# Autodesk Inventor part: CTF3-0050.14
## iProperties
Shininess: 64.0
Length Units: 11269
Angle Units: 11279
Time Units: 11290
Mass Units: 11283
Length Display Precision: 3
Angle Display Precision: 2
Compacted: True
Part Number: CTF3-0050.14
Document SubType Name: Modeling
Created: 2004-01
Designer: Lollo
Density: 0.0
Volumn: 0.0
Area: 0.0
PropertySet Name: Model Information
Control State: 0
Master: False
Checked Out: False
Author: Lollo
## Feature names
1. Estrusione1 [Extrusion]
2. Foro1 [Hole]
3. Smusso1 [Chamfer]
4. Serie circolare1 [Circular Pattern]
5. Smusso2 [Chamfer]
6. Foro3 [Hole]
7. Smusso3 [Chamfer]
8. Serie circolare2 [Circular Pattern]
